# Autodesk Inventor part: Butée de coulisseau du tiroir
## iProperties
Author: Flavien MARTY
Shininess: 25.0
PropertySet Name: _Private Model Information
Created: 2001-10
Part Number: Butée de coulisseau du tiroir
Material: Par défaut
Document SubType Name: Modélisation
Designer: Flavien MARTY
Control State: 0
Master: False
Checked Out: False
PropertySet Name: Design Tracking Control
Density: 0.0
Volumn: 0.0
Area: 0.0
PropertySet Name: Model Information
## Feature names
1. Base1
